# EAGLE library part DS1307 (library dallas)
I2C Serial RTC w/56 bytes battery backed RAM
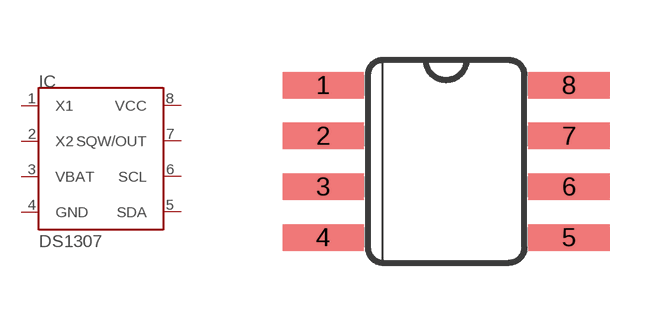
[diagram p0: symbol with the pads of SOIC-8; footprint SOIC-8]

Designator prefix IC

## DS1307  [SOIC-8]
1  X1  in
2  X2  out
3  VBAT  pwr
4  GND  pwr
5  SDA
6  SCL  in
7  SQW/OUT  out
8  VCC  pwr

## Footprint SOIC-8 (pad centres in mm)
smd 2.032 x 0.66: 1 -3.073,1.27; 2 -3.073,0; 3 -3.073,-1.27; 4 -3.073,-2.54; 5 3.073,-2.54; 6 3.073,-1.27; 7 3.073,0; 8 3.073,1.27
